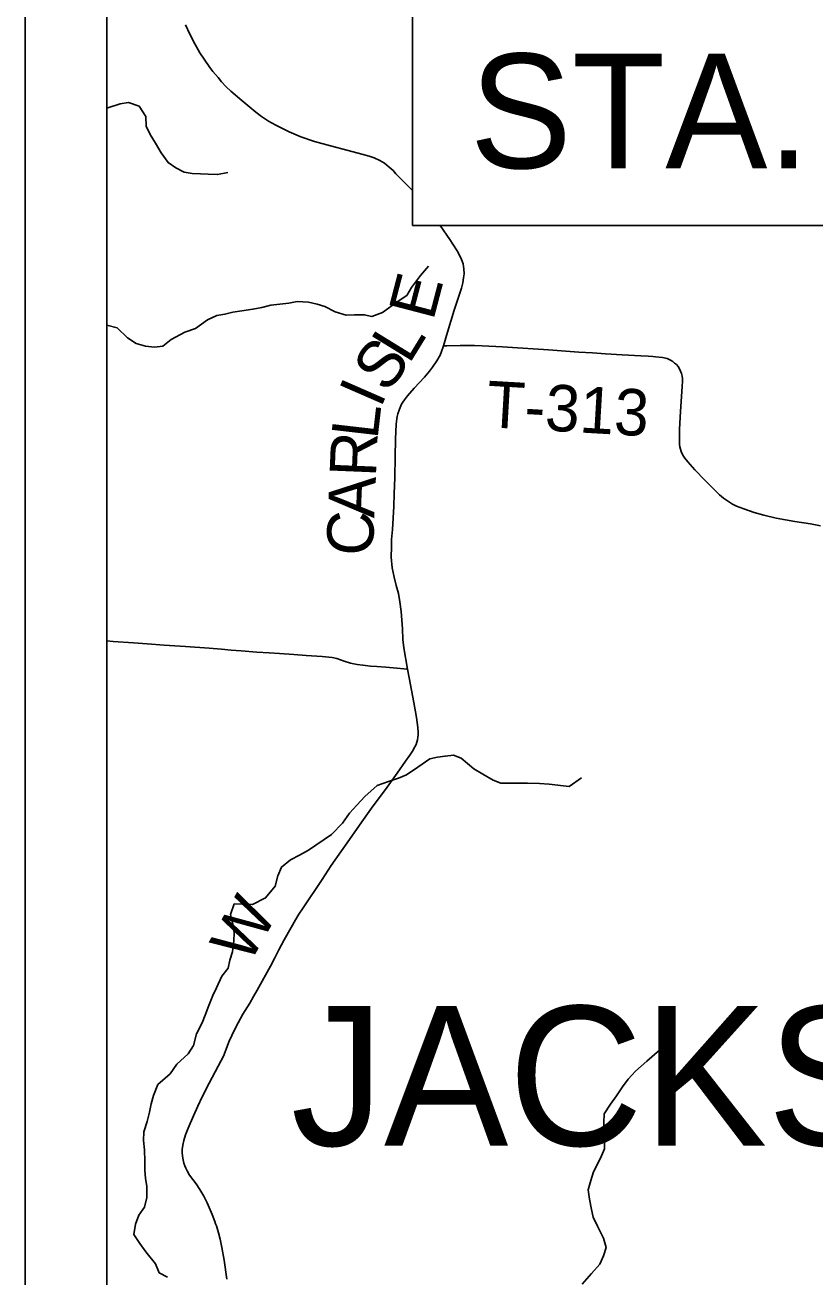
# Model space of a CAD drawing. Extents: x 0 to 34, y 0 to 22.
# Drawn here: x 23.917 to 24.883, y 15.788 to 17.319 of the extents above; entities that cross this region are included whole.
import ezdxf

# ---------------------------------------------------------------- set-up
doc = ezdxf.new("R2010")
doc.units = 0
for name, color, linetype in [('GM_X_Adjacent_County', 7, 'Continuous'), ('GM_X_County', 7, 'Continuous'), ('GM_X_County_Road', 7, 'Continuous'), ('GM_X_County_Road_Text', 7, 'Continuous'), ('GM_X_Minor_River', 7, 'Continuous'), ('GM_X_Township', 7, 'Continuous'), ('GM_X_Township_Road', 7, 'Continuous'), ('GM_X_Township_Road_Text', 7, 'Continuous'), ('GM_X_Township_Text', 7, 'Continuous'), ('SH_Data', 7, 'Continuous'), ('SH_Text', 7, 'Continuous')]:
    doc.layers.add(name, color=color, linetype=linetype)

msp = doc.modelspace()

# ---------------------------------------------------------------- linework, layer by layer
at = {"layer": 'GM_X_Adjacent_County'}
msp.add_lwpolyline([(24.0167, 18.0693), (24.0167, 14.1), (30.8167, 14.1), (30.8167, 17.8174)], dxfattribs=at)
at = {"layer": 'GM_X_County'}
msp.add_lwpolyline([(24.0167, 18.0693), (24.0167, 14.1), (30.8167, 14.1), (30.8167, 17.8174)], dxfattribs=at)
at = {"layer": 'GM_X_County_Road'}
for points in [[(24.3906, 17.1166), (24.3789, 17.1282), (24.3703, 17.137), (24.3668, 17.1407), (24.3622, 17.1451), (24.3562, 17.1498), (24.3506, 17.1531), (24.3435, 17.1562), (24.3375, 17.1584), (24.3288, 17.1607), (24.3119, 17.1652), (24.2902, 17.171), (24.2709, 17.1765), (24.2541, 17.1821), (24.2399, 17.1882), (24.2316, 17.1923), (24.2233, 17.1963), (24.2145, 17.2014), (24.206, 17.2071), (24.1989, 17.2122), (24.1915, 17.2183), (24.1817, 17.2263), (24.1683, 17.2377), (24.1626, 17.2431), (24.157, 17.2493), (24.1527, 17.2546), (24.1465, 17.2618), (24.1429, 17.2669), (24.1356, 17.277), (24.1305, 17.2849), (24.1242, 17.2956), (24.1184, 17.3077), (24.1131, 17.3188)], [(24.4286, 16.9265), (24.4336, 16.9431), (24.4417, 16.97), (24.4466, 16.9847), (24.4504, 16.9971), (24.452, 17.0035), (24.4531, 17.0097), (24.4537, 17.0146), (24.4535, 17.0206), (24.4531, 17.0236), (24.4525, 17.0266), (24.4506, 17.0322), (24.4481, 17.0375), (24.4452, 17.0427), (24.4399, 17.0507), (24.4362, 17.0567), (24.4246, 17.0737)], [(24.3846, 16.5313), (24.3799, 16.5572), (24.3789, 16.5675), (24.3783, 16.5807), (24.3766, 16.6015), (24.3752, 16.6136), (24.3733, 16.6237), (24.3707, 16.6335), (24.3681, 16.6437), (24.3657, 16.6549), (24.3644, 16.6681), (24.3647, 16.6807), (24.365, 16.6896), (24.366, 16.7019), (24.3676, 16.73), (24.3681, 16.7457), (24.3689, 16.7654), (24.3694, 16.7907), (24.3699, 16.8126), (24.3707, 16.8308), (24.3714, 16.8371), (24.3719, 16.8402), (24.3727, 16.8432), (24.3747, 16.8492), (24.3773, 16.855), (24.3788, 16.8577), (24.3806, 16.8604), (24.3844, 16.8653), (24.3927, 16.8746), (24.4052, 16.8883), (24.4112, 16.8954), (24.415, 16.9003), (24.4202, 16.908), (24.4244, 16.9153), (24.4262, 16.9195), (24.4283, 16.9253), (24.4286, 16.9265)], [(24.1634, 15.7853), (24.1601, 15.8085), (24.1572, 15.8241), (24.1552, 15.8344), (24.1535, 15.8418), (24.1508, 15.8504), (24.1498, 15.8532), (24.1488, 15.856), (24.1454, 15.8645), (24.1393, 15.8786), (24.1352, 15.8869), (24.1306, 15.895), (24.1258, 15.902), (24.118, 15.9126), (24.115, 15.9178), (24.1132, 15.9212), (24.1121, 15.9239), (24.111, 15.9271), (24.1095, 15.9332), (24.1089, 15.9394), (24.1089, 15.944), (24.1095, 15.9492), (24.1109, 15.955), (24.1131, 15.9617), (24.1161, 15.9698), (24.1227, 15.9851), (24.128, 15.9968), (24.1333, 16.0081), (24.1419, 16.025), (24.153, 16.0456), (24.1593, 16.0579), (24.1665, 16.0762), (24.173, 16.0904), (24.1772, 16.0986), (24.1832, 16.1092), (24.1886, 16.1183), (24.1916, 16.123), (24.196, 16.1308), (24.2007, 16.1387), (24.2068, 16.1496), (24.2169, 16.1682), (24.2221, 16.1783), (24.2271, 16.1879), (24.2338, 16.2004), (24.2422, 16.2155), (24.2473, 16.2245), (24.2517, 16.2316), (24.256, 16.2381), (24.2799, 16.2742), (24.291, 16.2912), (24.3039, 16.3092), (24.3106, 16.3189), (24.3258, 16.3406), (24.3403, 16.3614), (24.3594, 16.387), (24.3718, 16.4042), (24.3819, 16.4186), (24.3873, 16.4259), (24.3906, 16.431), (24.3936, 16.4364), (24.3949, 16.4391), (24.3959, 16.442), (24.3967, 16.4449), (24.3972, 16.4479), (24.3975, 16.4509), (24.3975, 16.4539), (24.3971, 16.46), (24.3964, 16.4661), (24.3954, 16.472), (24.3922, 16.4903), (24.3865, 16.5207), (24.3846, 16.5313)]]:
    msp.add_lwpolyline(points, dxfattribs=at)
at = {"layer": 'GM_X_Minor_River'}
for points in [[(24.0167, 17.2171), (24.0193, 17.2179), (24.033, 17.2225), (24.0432, 17.224), (24.0561, 17.2195), (24.0645, 17.207), (24.065, 17.1952), (24.0699, 17.185), (24.0761, 17.1744), (24.0833, 17.1626), (24.0917, 17.1505), (24.1012, 17.1441), (24.1115, 17.1388), (24.121, 17.1373), (24.1312, 17.137), (24.1407, 17.1363), (24.1521, 17.1359), (24.1646, 17.1386)], [(24.0167, 16.9519), (24.0292, 16.9487), (24.0421, 16.9362), (24.0524, 16.9294), (24.0642, 16.9261), (24.0752, 16.925), (24.0851, 16.9261), (24.0956, 16.9341), (24.1123, 16.9433), (24.1252, 16.9479), (24.1399, 16.9582), (24.1513, 16.9635), (24.1612, 16.9651), (24.171, 16.9678), (24.182, 16.9693), (24.1953, 16.9713), (24.2063, 16.9732), (24.2173, 16.9763), (24.2393, 16.9786), (24.2495, 16.9806), (24.2635, 16.9799), (24.2738, 16.9776), (24.2833, 16.9746), (24.2958, 16.9682), (24.3095, 16.9641), (24.3198, 16.9645), (24.3315, 16.9645), (24.341, 16.9623), (24.3539, 16.9673), (24.3732, 16.981), (24.3838, 16.9882), (24.3894, 16.9977), (24.4004, 17.0126), (24.4102, 17.024)], [(24.3612, 16.394), (24.3733, 16.3978), (24.3832, 16.4021), (24.3972, 16.4112), (24.4116, 16.4215), (24.421, 16.4234), (24.4305, 16.425), (24.4408, 16.4262), (24.4503, 16.4224), (24.4655, 16.4095), (24.4765, 16.4027), (24.4891, 16.3956), (24.4986, 16.3918), (24.5312, 16.3919), (24.546, 16.3912), (24.5578, 16.3905)], [(24.0909, 15.7876), (24.0806, 15.7932), (24.0764, 15.8039), (24.0646, 15.8186), (24.057, 15.8288), (24.0497, 15.8398), (24.0516, 15.8524), (24.0557, 15.8634), (24.0629, 15.8733), (24.0658, 15.8854), (24.0658, 15.8991), (24.0642, 15.9086), (24.0631, 15.9185), (24.063, 15.9295), (24.0626, 15.9435), (24.0614, 15.9549), (24.0621, 15.9655), (24.0662, 15.9781), (24.0688, 15.9895), (24.0711, 15.9997), (24.0737, 16.01), (24.0789, 16.0233), (24.0941, 16.0366), (24.1024, 16.0481), (24.116, 16.061), (24.1227, 16.0709), (24.1265, 16.0853), (24.1333, 16.0986), (24.137, 16.1082), (24.1415, 16.1199), (24.1464, 16.1321), (24.1509, 16.1416), (24.1573, 16.1557), (24.1652, 16.1656), (24.1671, 16.1754), (24.1705, 16.1857), (24.1719, 16.199), (24.1726, 16.2089), (24.1707, 16.2199), (24.168, 16.2313), (24.1725, 16.2442), (24.1824, 16.2438), (24.1949, 16.2435), (24.2108, 16.2515), (24.2225, 16.266), (24.2259, 16.2785), (24.2304, 16.2892), (24.2413, 16.2979), (24.2523, 16.3037), (24.2633, 16.3098), (24.2917, 16.3289), (24.3049, 16.343), (24.3136, 16.3551), (24.3226, 16.365), (24.3321, 16.3753), (24.3472, 16.389), (24.3612, 16.394)], [(24.5578, 16.3905), (24.5822, 16.3879), (24.5973, 16.3982)], [(24.5981, 15.7794), (24.6094, 15.7923), (24.6196, 15.8037), (24.6241, 15.814), (24.6274, 15.8242), (24.624, 15.8356), (24.6167, 15.85), (24.6117, 15.861), (24.6094, 15.8705), (24.6071, 15.883), (24.6055, 15.8944), (24.6089, 15.9061), (24.6119, 15.9164), (24.6205, 15.9331), (24.6254, 15.9449), (24.6253, 15.9574), (24.6245, 15.9673), (24.6245, 15.9771), (24.6252, 15.9877), (24.6327, 15.9995), (24.6403, 16.0094), (24.6474, 16.0205), (24.6545, 16.03), (24.6632, 16.0395), (24.6772, 16.052), (24.6926, 16.0654), (24.7051, 16.0764)]]:
    msp.add_lwpolyline(points, dxfattribs=at)
at = {"layer": 'GM_X_Township'}
msp.add_lwpolyline([(24.0167, 18.0693), (24.0167, 14.1), (26.1244, 14.1)], dxfattribs=at)
at = {"layer": 'GM_X_Township_Road'}
for points in [[(24.4286, 16.9265), (24.4327, 16.9266), (24.4488, 16.9269), (24.4586, 16.9269), (24.4666, 16.9268), (24.4759, 16.9264), (24.5006, 16.9252), (24.513, 16.9245), (24.5571, 16.9218), (24.5941, 16.9188), (24.6108, 16.9178), (24.6265, 16.9167), (24.6471, 16.9156), (24.6698, 16.9144), (24.6788, 16.914), (24.6847, 16.9135), (24.688, 16.9132), (24.6963, 16.9123), (24.7022, 16.9109), (24.7061, 16.9091), (24.7089, 16.9073), (24.7112, 16.9055), (24.7134, 16.9036), (24.7155, 16.9013), (24.7173, 16.8986), (24.7185, 16.8956), (24.7197, 16.8927), (24.7204, 16.8896), (24.7207, 16.8864), (24.7207, 16.8832), (24.7204, 16.877), (24.719, 16.8585), (24.7183, 16.8461), (24.7172, 16.8245), (24.717, 16.8121), (24.7173, 16.806), (24.7177, 16.803), (24.7184, 16.8), (24.7193, 16.7972), (24.7205, 16.7945), (24.722, 16.7918), (24.7237, 16.7893), (24.7275, 16.7846), (24.7359, 16.7751), (24.7481, 16.7624), (24.758, 16.7523), (24.7662, 16.7443), (24.771, 16.7402), (24.777, 16.736), (24.7819, 16.7329), (24.7869, 16.7305), (24.7959, 16.7271), (24.8083, 16.7228), (24.8204, 16.7195), (24.8353, 16.7159), (24.8581, 16.7119), (24.8774, 16.7088), (24.8896, 16.7066)], [(24.0167, 16.566), (24.0244, 16.5651), (24.0492, 16.5632), (24.0659, 16.5621), (24.0867, 16.5605), (24.1131, 16.5588), (24.1417, 16.5569), (24.1568, 16.5556), (24.1689, 16.5545), (24.1811, 16.5535), (24.2, 16.5519), (24.2153, 16.5511), (24.2279, 16.5502), (24.2456, 16.549)], [(24.2456, 16.549), (24.2604, 16.5479), (24.28, 16.5465), (24.2922, 16.5453), (24.2982, 16.5441), (24.3071, 16.5409), (24.3149, 16.5387), (24.323, 16.5367), (24.33, 16.5359), (24.3394, 16.535), (24.3471, 16.5346), (24.3578, 16.5336), (24.3716, 16.5325), (24.38, 16.5317), (24.3846, 16.5313)]]:
    msp.add_lwpolyline(points, dxfattribs=at)
at = {"layer": 'SH_Data'}
for points in [[(23.9167, 21), (30.9167, 21), (30.9167, 14), (23.9167, 14)], [(24.0167, 20.9), (30.8167, 20.9), (30.8167, 14.1), (24.0167, 14.1)]]:
    msp.add_lwpolyline(points, close=True, dxfattribs=at)
at = {"layer": 'SH_Text'}
msp.add_lwpolyline([(24.3906, 17.0737), (25.8632, 17.0737), (25.8632, 17.5637), (24.3906, 17.5637)], close=True, dxfattribs=at)

# ---------------------------------------------------------------- texts
at = {"layer": 'GM_X_County_Road_Text'}
for s, rotation, p in [('E', 75.386, (24.4158, 16.9561)), ('S', 52.0733, (24.3588, 16.8672)), ('L', 58.3887, (24.3863, 16.903)), ('I', 66.3965, (24.3514, 16.849)), ('L', 83.4331, (24.3477, 16.8111)), ('R', 87.6145, (24.3458, 16.7655)), ('A', 87.6487, (24.3438, 16.7156)), ('C', 87.6459, (24.3419, 16.669)), ('W', 60.5261, (24.1905, 16.1689))]:
    msp.add_text(s, height=0.0568, rotation=rotation, dxfattribs=at).set_placement(p)
at = {"layer": 'GM_X_Township_Road_Text'}
msp.add_text('T-313', height=0.05682, rotation=356.6983, dxfattribs=at).set_placement((24.48, 16.8272))
at = {"layer": 'GM_X_Township_Text'}
msp.add_text('JACKSON', height=0.17045, rotation=0, dxfattribs=at).set_placement((24.2418, 15.9487))
at = {"layer": 'SH_Text'}
msp.add_text('STA. 1129+25', height=0.14, dxfattribs=at).set_placement((24.4606, 17.1437))

doc.saveas('drawing.dxf')
